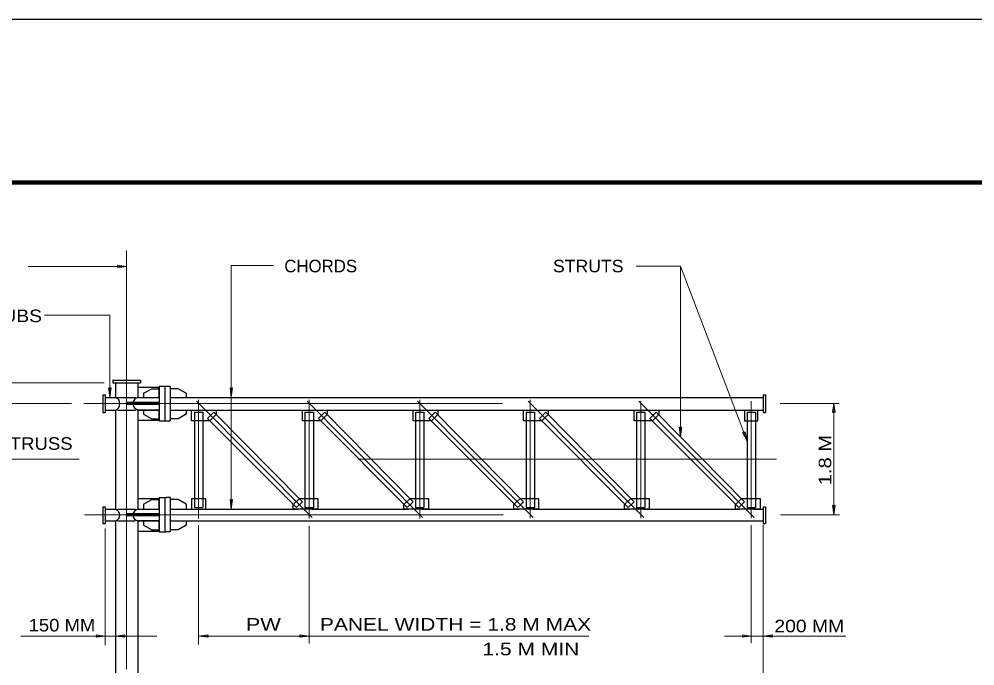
# Model space of a CAD drawing. Extents: x 312601.858 to 312602.699, y 144420.109 to 144420.704.
# Drawn here: x 312601.9725 to 312602.2008, y 144420.549 to 144420.7035 of the extents above; entities that cross this region are included whole.
import ezdxf
from ezdxf.enums import TextEntityAlignment as Align

# ---------------------------------------------------------------- set-up
doc = ezdxf.new("R2010")
doc.units = 0
doc.header["$LTSCALE"] = 0.0012
doc.linetypes.add('DOT_DASHED', pattern=[7.7, 5, -1.2, 0.3, -1.2])
doc.linetypes.add('MEDIUM_DASHED', pattern=[4.5, 3, -1.5])
for name, color, linetype, lineweight in [('1', 7, 'Continuous', 13), ('2', 7, 'Continuous', 25), ('39', 7, 'Continuous', 13)]:
    doc.layers.add(name, color=color, linetype=linetype, lineweight=lineweight)

msp = doc.modelspace()

# ---------------------------------------------------------------- linework, layer by layer
at = {"layer": '1', "linetype": 'DOT_DASHED'}
for p, q in [((312601.9982, 144420.6482), (312601.9982, 144420.4826)), ((312602.0425, 144420.5844), (312602.0149, 144420.6122)), ((312602.0154, 144420.6125), (312602.0154, 144420.5842)), ((312602.0689, 144420.5844), (312602.0413, 144420.6122)), ((312602.0418, 144420.6125), (312602.0418, 144420.5842)), ((312602.0953, 144420.5844), (312602.0677, 144420.6122)), ((312602.0682, 144420.6125), (312602.0682, 144420.5842)), ((312602.1217, 144420.5844), (312602.0941, 144420.6122)), ((312602.0946, 144420.6125), (312602.0946, 144420.5843)), ((312602.1481, 144420.5844), (312602.1205, 144420.6122)), ((312602.121, 144420.6122), (312602.121, 144420.5843)), ((312602.1474, 144420.6122), (312602.1474, 144420.5843)), ((312601.988, 144420.6117), (312602.1531, 144420.6117)), ((312602.1534, 144420.5984), (312601.9892, 144420.5984)), ((312601.9881, 144420.5851), (312602.153, 144420.5851)), ((312602.0154, 144420.5811), (312602.0154, 144420.581))]:
    msp.add_line(p, q, dxfattribs=at)
at = {"layer": '1'}
for p, q in [((312601.9747, 144420.6444), (312601.9982, 144420.6444)), ((312602.0333, 144420.6446), (312602.0232, 144420.6446)), ((312602.1305, 144420.6445), (312602.1464, 144420.6027)), ((312601.9942, 144420.6328), (312601.9786, 144420.6328)), ((312601.9942, 144420.6328), (312601.9942, 144420.6131)), ((312601.9675, 144420.6166), (312601.9928, 144420.6166)), ((312601.9955, 144420.6166), (312602.0009, 144420.6166)), ((312602.0022, 144420.6141), (312602.0042, 144420.6152)), ((312602.0042, 144420.6152), (312602.0053, 144420.6152)), ((312602.0105, 144420.6152), (312602.0093, 144420.6152)), ((312601.9931, 144420.6131), (312601.9931, 144420.6103)), ((312602.0022, 144420.6141), (312602.0022, 144420.6131)), ((312602.0124, 144420.6141), (312602.0124, 144420.6132)), ((312602.0124, 144420.6141), (312602.0124, 144420.6131)), ((312601.9402, 144420.6117), (312601.985, 144420.6117)), ((312602.0464, 144420.6101), (312602.047, 144420.6101)), ((312602.0728, 144420.6101), (312602.0734, 144420.6101)), ((312602.099, 144420.6101), (312602.0998, 144420.6101)), ((312602.1543, 144420.6117), (312602.1684, 144420.6117)), ((312602.1671, 144420.6117), (312602.1671, 144420.5851)), ((312602.0022, 144420.6091), (312602.0042, 144420.608)), ((312602.0042, 144420.608), (312602.0053, 144420.608)), ((312602.0105, 144420.608), (312602.0093, 144420.608)), ((312602.0124, 144420.6091), (312602.0105, 144420.608)), ((312602.0408, 144420.6094), (312602.0408, 144420.6093)), ((312602.0672, 144420.6094), (312602.0672, 144420.6093)), ((312602.0936, 144420.6094), (312602.0936, 144420.6093)), ((312602.12, 144420.6094), (312602.12, 144420.6093)), ((312601.9869, 144420.5984), (312601.9398, 144420.5984)), ((312602.0022, 144420.5876), (312602.0042, 144420.5887)), ((312602.0022, 144420.5876), (312602.0042, 144420.5887)), ((312602.0022, 144420.5876), (312602.0022, 144420.5866)), ((312602.0022, 144420.5876), (312602.0022, 144420.5866)), ((312602.0042, 144420.5887), (312602.0053, 144420.5887)), ((312602.0042, 144420.5887), (312602.0053, 144420.5887)), ((312602.0105, 144420.5887), (312602.0093, 144420.5887)), ((312602.0105, 144420.5887), (312602.0093, 144420.5887)), ((312602.0124, 144420.5876), (312602.0105, 144420.5887)), ((312602.0124, 144420.5876), (312602.0105, 144420.5887)), ((312602.0124, 144420.5876), (312602.0124, 144420.5866)), ((312602.0124, 144420.5876), (312602.0124, 144420.5867)), ((312602.0124, 144420.5876), (312602.0124, 144420.5866)), ((312602.0124, 144420.5876), (312602.0124, 144420.5867)), ((312602.0124, 144420.5876), (312602.0124, 144420.5866)), ((312602.0392, 144420.5864), (312602.0386, 144420.5864)), ((312602.0425, 144420.5864), (312602.047, 144420.5864)), ((312602.0656, 144420.5864), (312602.065, 144420.5864)), ((312602.0655, 144420.5864), (312602.0656, 144420.5864)), ((312602.092, 144420.5864), (312602.0914, 144420.5864)), ((312602.0953, 144420.5864), (312602.0998, 144420.5864)), ((312602.1184, 144420.5864), (312602.1178, 144420.5864)), ((312602.1183, 144420.5864), (312602.1184, 144420.5864)), ((312602.1447, 144420.5864), (312602.1448, 144420.5864)), ((312602.1544, 144420.5851), (312602.1685, 144420.5851)), ((312602.0022, 144420.5836), (312602.0022, 144420.5826)), ((312602.0022, 144420.5826), (312602.0042, 144420.5815)), ((312602.0022, 144420.5826), (312602.0042, 144420.5815)), ((312602.0124, 144420.5826), (312602.0105, 144420.5815)), ((312602.0124, 144420.5826), (312602.0105, 144420.5815)), ((312602.0124, 144420.5836), (312602.0124, 144420.5826)), ((312602.0124, 144420.5836), (312602.0124, 144420.5826)), ((312602.0154, 144420.5826), (312602.0154, 144420.5541)), ((312602.0418, 144420.5824), (312602.0418, 144420.5543)), ((312602.1474, 144420.5826), (312602.1474, 144420.5544)), ((312602.1502, 144420.5827), (312602.1502, 144420.531)), ((312601.9931, 144420.5818), (312601.9931, 144420.5539)), ((312602.0042, 144420.5815), (312602.0053, 144420.5815)), ((312602.0105, 144420.5815), (312602.0093, 144420.5815)), ((312602.0105, 144420.5815), (312602.0093, 144420.5815))]:
    msp.add_line(p, q, dxfattribs=at)
at = {"layer": '1', "lineweight": 25}
for p, q in [((312601.9949, 144420.6172), (312601.9949, 144420.6166)), ((312601.9949, 144420.6166), (312602.0015, 144420.6166)), ((312601.9955, 144420.6166), (312601.9955, 144420.6131)), ((312602.0009, 144420.6166), (312602.0009, 144420.6131)), ((312602.0022, 144420.6141), (312602.0042, 144420.6152)), ((312602.0042, 144420.6152), (312602.006, 144420.6152)), ((312602.0086, 144420.6157), (312602.006, 144420.6157)), ((312602.0105, 144420.6152), (312602.0086, 144420.6152)), ((312602.0124, 144420.6141), (312602.0105, 144420.6152)), ((312602.0124, 144420.6141), (312602.0105, 144420.6152)), ((312601.9925, 144420.6137), (312601.9931, 144420.6137)), ((312601.9925, 144420.6137), (312601.9925, 144420.6095)), ((312601.9931, 144420.6137), (312601.9931, 144420.6095)), ((312601.9931, 144420.6131), (312601.9955, 144420.6131)), ((312602.0009, 144420.6131), (312602.006, 144420.6131)), ((312602.0022, 144420.6141), (312602.0022, 144420.6131)), ((312602.0086, 144420.6131), (312602.1502, 144420.6131)), ((312602.0124, 144420.6141), (312602.0124, 144420.6132)), ((312602.0124, 144420.6141), (312602.0124, 144420.6131)), ((312602.1502, 144420.6137), (312602.1502, 144420.6095)), ((312602.1502, 144420.6137), (312602.1508, 144420.6137)), ((312602.1508, 144420.6137), (312602.1508, 144420.6095)), ((312601.9931, 144420.6101), (312601.9955, 144420.6101)), ((312601.9955, 144420.6101), (312601.9955, 144420.5864)), ((312602.0009, 144420.6101), (312602.0009, 144420.5864)), ((312602.0009, 144420.6101), (312602.006, 144420.6101)), ((312602.0022, 144420.6101), (312602.0022, 144420.6091)), ((312602.0086, 144420.6101), (312602.0124, 144420.6101)), ((312602.0124, 144420.6101), (312602.0148, 144420.6101)), ((312602.0124, 144420.6101), (312602.0124, 144420.6091)), ((312602.0124, 144420.6101), (312602.0124, 144420.6091)), ((312602.0144, 144420.6096), (312602.0144, 144420.5868)), ((312602.0164, 144420.6096), (312602.0164, 144420.5868)), ((312602.0402, 144420.5882), (312602.019, 144420.6096)), ((312602.0408, 144420.6096), (312602.0408, 144420.5868)), ((312602.0428, 144420.6096), (312602.0428, 144420.5868)), ((312602.0449, 144420.6101), (312602.0676, 144420.6101)), ((312602.0666, 144420.5882), (312602.0455, 144420.6096)), ((312602.0672, 144420.6096), (312602.0672, 144420.5868)), ((312602.0692, 144420.6096), (312602.0692, 144420.5868)), ((312602.0714, 144420.6101), (312602.094, 144420.6101)), ((312602.093, 144420.5882), (312602.0719, 144420.6096)), ((312602.0936, 144420.6096), (312602.0936, 144420.5868)), ((312602.0956, 144420.6096), (312602.0956, 144420.5868)), ((312602.0977, 144420.6101), (312602.1204, 144420.6101)), ((312602.1194, 144420.5882), (312602.0983, 144420.6096)), ((312602.12, 144420.6096), (312602.12, 144420.5868)), ((312602.122, 144420.6096), (312602.122, 144420.5868)), ((312602.1241, 144420.6101), (312602.1502, 144420.6101)), ((312602.1458, 144420.5882), (312602.1247, 144420.6096)), ((312602.1253, 144420.6101), (312602.1262, 144420.6101)), ((312602.1464, 144420.6096), (312602.1464, 144420.5868)), ((312602.1484, 144420.6096), (312602.1484, 144420.5868)), ((312601.9925, 144420.6095), (312601.9931, 144420.6095)), ((312602.0022, 144420.6091), (312602.0042, 144420.608)), ((312602.0042, 144420.608), (312602.006, 144420.608)), ((312602.006, 144420.6075), (312602.0086, 144420.6075)), ((312602.0105, 144420.608), (312602.0086, 144420.608)), ((312602.0124, 144420.6091), (312602.0105, 144420.608)), ((312602.0144, 144420.6094), (312602.0144, 144420.6093)), ((312602.0388, 144420.5868), (312602.0175, 144420.6081)), ((312602.0652, 144420.5868), (312602.044, 144420.6081)), ((312602.0916, 144420.5868), (312602.0704, 144420.6081)), ((312602.118, 144420.5868), (312602.0968, 144420.6081)), ((312602.1444, 144420.5868), (312602.1232, 144420.6081)), ((312602.1502, 144420.6095), (312602.1508, 144420.6095)), ((312602.006, 144420.5892), (312602.0077, 144420.5892)), ((312602.0086, 144420.5892), (312602.0077, 144420.5892)), ((312601.9925, 144420.587), (312601.9925, 144420.583)), ((312601.9925, 144420.587), (312601.9931, 144420.587)), ((312601.9931, 144420.587), (312601.9931, 144420.583)), ((312602.0022, 144420.5876), (312602.0042, 144420.5887)), ((312602.0022, 144420.5876), (312602.0022, 144420.5864)), ((312602.0042, 144420.5887), (312602.006, 144420.5887)), ((312602.0105, 144420.5887), (312602.0086, 144420.5887)), ((312602.0124, 144420.5876), (312602.0105, 144420.5887)), ((312602.0124, 144420.5876), (312602.0124, 144420.5864)), ((312602.1502, 144420.587), (312602.1502, 144420.583)), ((312602.1502, 144420.587), (312602.1508, 144420.587)), ((312602.1508, 144420.587), (312602.1508, 144420.583)), ((312601.9931, 144420.5864), (312601.9955, 144420.5864)), ((312602.0009, 144420.5864), (312602.006, 144420.5864)), ((312602.0086, 144420.5864), (312602.0161, 144420.5864)), ((312602.016, 144420.5864), (312602.0392, 144420.5864)), ((312602.0424, 144420.5864), (312602.0656, 144420.5864)), ((312602.0688, 144420.5864), (312602.092, 144420.5864)), ((312602.0689, 144420.5864), (312602.0734, 144420.5864)), ((312602.0952, 144420.5864), (312602.1184, 144420.5864)), ((312602.1216, 144420.5864), (312602.1447, 144420.5864)), ((312602.1217, 144420.5864), (312602.1262, 144420.5864)), ((312602.148, 144420.5864), (312602.1502, 144420.5864)), ((312601.9925, 144420.583), (312601.9931, 144420.583)), ((312601.9931, 144420.5836), (312601.9955, 144420.5836)), ((312601.9955, 144420.5836), (312601.9955, 144420.4967)), ((312602.0009, 144420.5836), (312602.0009, 144420.4967)), ((312602.0009, 144420.5836), (312602.006, 144420.5836)), ((312602.0022, 144420.5836), (312602.0022, 144420.5826)), ((312602.0022, 144420.5826), (312602.0042, 144420.5815)), ((312602.0086, 144420.5836), (312602.0124, 144420.5836)), ((312602.0124, 144420.5826), (312602.0105, 144420.5815)), ((312602.0122, 144420.5836), (312602.1502, 144420.5836)), ((312602.0124, 144420.5836), (312602.0124, 144420.5826)), ((312602.1502, 144420.583), (312602.1508, 144420.583)), ((312602.0042, 144420.5815), (312602.006, 144420.5815)), ((312602.006, 144420.581), (312602.0077, 144420.581)), ((312602.0086, 144420.581), (312602.0077, 144420.581)), ((312602.0105, 144420.5815), (312602.0086, 144420.5815))]:
    msp.add_line(p, q, dxfattribs=at)
at = {"layer": '1', "linetype": 'MEDIUM_DASHED', "lineweight": 25}
for p, q in [((312601.9959, 144420.6131), (312602.0004, 144420.6131)), ((312601.996, 144420.6101), (312602.0003, 144420.6101)), ((312601.996, 144420.5864), (312602.0003, 144420.5864)), ((312601.996, 144420.5836), (312602.0002, 144420.5836))]:
    msp.add_line(p, q, dxfattribs=at)
at = {"layer": '1'}
for points in [[(312601.996, 144420.6447), (312601.9982, 144420.6444), (312601.996, 144420.6441), (312601.9962, 144420.6444)], [(312601.996, 144420.6447), (312601.9982, 144420.6444), (312601.996, 144420.6441), (312601.9962, 144420.6444)], [(312601.9945, 144420.6154), (312601.9942, 144420.6131), (312601.9939, 144420.6154), (312601.9942, 144420.6151)], [(312601.9945, 144420.6154), (312601.9942, 144420.6131), (312601.9939, 144420.6154), (312601.9942, 144420.6151)], [(312602.0235, 144420.6154), (312602.0232, 144420.6131), (312602.0229, 144420.6154), (312602.0232, 144420.6151)], [(312602.1668, 144420.6095), (312602.1671, 144420.6117), (312602.1674, 144420.6095), (312602.1671, 144420.6097)], [(312602.1668, 144420.6095), (312602.1671, 144420.6117), (312602.1674, 144420.6095), (312602.1671, 144420.6097)], [(312602.1308, 144420.606), (312602.1305, 144420.6037), (312602.1302, 144420.606), (312602.1305, 144420.6057)], [(312602.1308, 144420.606), (312602.1305, 144420.6037), (312602.1302, 144420.606), (312602.1305, 144420.6057)], [(312602.1459, 144420.6049), (312602.1464, 144420.6027), (312602.1453, 144420.6047), (312602.1457, 144420.6046)], [(312602.1459, 144420.6049), (312602.1464, 144420.6027), (312602.1453, 144420.6047), (312602.1457, 144420.6046)], [(312602.0235, 144420.5887), (312602.0232, 144420.5864), (312602.0229, 144420.5887), (312602.0232, 144420.5884)], [(312602.0235, 144420.5887), (312602.0232, 144420.5864), (312602.0229, 144420.5887), (312602.0232, 144420.5884)], [(312602.1674, 144420.5874), (312602.1671, 144420.5851), (312602.1668, 144420.5874), (312602.1671, 144420.5871)], [(312602.1674, 144420.5874), (312602.1671, 144420.5851), (312602.1668, 144420.5874), (312602.1671, 144420.5871)], [(312601.9909, 144420.5564), (312601.9931, 144420.5561), (312601.9909, 144420.5558), (312601.9911, 144420.5561)], [(312601.9978, 144420.5558), (312601.9955, 144420.5561), (312601.9978, 144420.5564), (312601.9975, 144420.5561)], [(312602.0177, 144420.5558), (312602.0154, 144420.5561), (312602.0177, 144420.5564), (312602.0174, 144420.5561)], [(312602.0396, 144420.5564), (312602.0418, 144420.5561), (312602.0396, 144420.5558), (312602.0398, 144420.5561)], [(312602.1452, 144420.5564), (312602.1474, 144420.5561), (312602.1452, 144420.5558), (312602.1454, 144420.5561)], [(312602.1525, 144420.5558), (312602.1502, 144420.5561), (312602.1525, 144420.5564), (312602.1522, 144420.5561)], [(312602.1525, 144420.5558), (312602.1502, 144420.5561), (312602.1525, 144420.5564), (312602.1522, 144420.5561)]]:
    msp.add_lwpolyline(points, close=True, dxfattribs=at)
for points in [[(312602.0232, 144420.6446), (312602.0232, 144420.6131), (312602.0232, 144420.5864)], [(312602.1199, 144420.6445), (312602.1305, 144420.6445), (312602.1305, 144420.6037)], [(312602.0919, 144420.5864), (312602.092, 144420.5864), (312602.092, 144420.5864)], [(312602.1183, 144420.5864), (312602.1184, 144420.5864), (312602.1184, 144420.5864)], [(312601.9729, 144420.5561), (312601.9931, 144420.5561), (312601.9955, 144420.5561), (312602.0054, 144420.5561)], [(312602.0154, 144420.5561), (312602.0418, 144420.5561), (312602.1086, 144420.5561)], [(312602.141, 144420.5561), (312602.1474, 144420.5561), (312602.1501, 144420.5561), (312602.17, 144420.5561)]]:
    msp.add_lwpolyline(points, dxfattribs=at)
at = {"layer": '1', "lineweight": 25}
msp.add_lwpolyline([(312601.9949, 144420.6172), (312602.0015, 144420.6172), (312602.0015, 144420.6166)], dxfattribs=at)
for points in [[(312602.0009, 144420.6131), (312602.006, 144420.6131), (312602.006, 144420.6155), (312602.0009, 144420.6155)], [(312601.9982, 144420.6115), (312602.006, 144420.6115), (312602.006, 144420.6119), (312601.9982, 144420.6119)], [(312602.0009, 144420.6077), (312602.006, 144420.6077), (312602.006, 144420.6101), (312602.0009, 144420.6101)], [(312602.0009, 144420.5864), (312602.006, 144420.5864), (312602.006, 144420.5889), (312602.0009, 144420.5889)], [(312601.9982, 144420.5849), (312602.006, 144420.5849), (312602.006, 144420.5853), (312601.9982, 144420.5853)], [(312602.0009, 144420.5812), (312602.006, 144420.5812), (312602.006, 144420.5836), (312602.0009, 144420.5836)]]:
    msp.add_lwpolyline(points, close=True, dxfattribs=at)
for centre, radius, start, end in [((312601.995032, 144420.6116), 0.0015714, 287.33425, 72.66575), ((312602.001233, 144420.6116), 0.0015366, 102.52881, 168.93478), ((312602.001233, 144420.6116), 0.0015366, 183.81131, 257.47119), ((312601.995164, 144420.585), 0.0014398, 283.5098, 76.49019), ((312602.001113, 144420.585), 0.001416, 179.71208, 180.30501), ((312602.001113, 144420.585), 0.001416, 184.13614, 261.3692), ((312602.001113, 144420.585), 0.001416, 98.6308, 170.66727)]:
    msp.add_arc(centre, radius, start, end, dxfattribs=at)
at = {"layer": '2'}
for p, q in [((312602.006, 144420.6157), (312602.006, 144420.6075)), ((312602.0073, 144420.6157), (312602.0073, 144420.6075)), ((312602.0086, 144420.6157), (312602.0086, 144420.6075)), ((312602.0086, 144420.6101), (312602.1137, 144420.6101)), ((312602.0144, 144420.6096), (312602.0164, 144420.6096)), ((312602.0175, 144420.6081), (312602.019, 144420.6096)), ((312602.0408, 144420.6096), (312602.0428, 144420.6096)), ((312602.0455, 144420.6096), (312602.044, 144420.6081)), ((312602.0672, 144420.6096), (312602.0692, 144420.6096)), ((312602.0719, 144420.6096), (312602.0704, 144420.6081)), ((312602.0936, 144420.6096), (312602.0956, 144420.6096)), ((312602.0983, 144420.6096), (312602.0968, 144420.6081)), ((312602.12, 144420.6096), (312602.122, 144420.6096)), ((312602.1247, 144420.6096), (312602.1232, 144420.6081)), ((312602.1464, 144420.6096), (312602.1484, 144420.6096)), ((312602.006, 144420.5892), (312602.006, 144420.581)), ((312602.0073, 144420.5892), (312602.0073, 144420.581)), ((312602.0086, 144420.5892), (312602.0086, 144420.581)), ((312602.0144, 144420.5868), (312602.0164, 144420.5868)), ((312602.0388, 144420.5868), (312602.0402, 144420.5882)), ((312602.0408, 144420.5868), (312602.0428, 144420.5868)), ((312602.0652, 144420.5868), (312602.0666, 144420.5882)), ((312602.0672, 144420.5868), (312602.0692, 144420.5868)), ((312602.0916, 144420.5868), (312602.093, 144420.5882)), ((312602.0936, 144420.5868), (312602.0956, 144420.5868)), ((312602.118, 144420.5868), (312602.1194, 144420.5882)), ((312602.12, 144420.5868), (312602.122, 144420.5868)), ((312602.1444, 144420.5868), (312602.1458, 144420.5882)), ((312602.1464, 144420.5868), (312602.1484, 144420.5868))]:
    msp.add_line(p, q, dxfattribs=at)
for points in [[(312602.0137, 144420.6101), (312602.0196, 144420.6101), (312602.0196, 144420.609), (312602.0181, 144420.6075), (312602.0137, 144420.6075)], [(312602.0402, 144420.6101), (312602.0461, 144420.6101), (312602.0461, 144420.609), (312602.0446, 144420.6075), (312602.0402, 144420.6075)], [(312602.0666, 144420.6101), (312602.0725, 144420.6101), (312602.0725, 144420.609), (312602.071, 144420.6075), (312602.0666, 144420.6075)], [(312602.093, 144420.6101), (312602.0989, 144420.6101), (312602.0989, 144420.609), (312602.0974, 144420.6075), (312602.093, 144420.6075)], [(312602.1194, 144420.6101), (312602.1253, 144420.6101), (312602.1253, 144420.609), (312602.1238, 144420.6075), (312602.1194, 144420.6075)], [(312602.0439, 144420.5864), (312602.038, 144420.5864), (312602.038, 144420.5875), (312602.0395, 144420.589), (312602.0439, 144420.589)], [(312602.0703, 144420.5864), (312602.0644, 144420.5864), (312602.0644, 144420.5875), (312602.0659, 144420.589), (312602.0703, 144420.589)], [(312602.0966, 144420.5864), (312602.0907, 144420.5864), (312602.0907, 144420.5875), (312602.0922, 144420.589), (312602.0966, 144420.589)], [(312602.123, 144420.5864), (312602.1171, 144420.5864), (312602.1171, 144420.5875), (312602.1186, 144420.589), (312602.123, 144420.589)], [(312602.1495, 144420.5864), (312602.1436, 144420.5864), (312602.1436, 144420.5875), (312602.1451, 144420.589), (312602.1495, 144420.589)]]:
    msp.add_lwpolyline(points, close=True, dxfattribs=at)
for points in [[(312602.1458, 144420.6101), (312602.1458, 144420.6075), (312602.149, 144420.6075), (312602.149, 144420.6101)], [(312602.0138, 144420.5864), (312602.0138, 144420.589), (312602.017, 144420.589), (312602.017, 144420.5864)]]:
    msp.add_lwpolyline(points, dxfattribs=at)
at = {"layer": '39', "lineweight": 25}
msp.add_line((312601.8578, 144420.7035), (312602.6988, 144420.7035), dxfattribs=at)
at = {"layer": '39', "lineweight": 158}
msp.add_line((312601.9088, 144420.6645), (312602.6838, 144420.6645), dxfattribs=at)

# ---------------------------------------------------------------- texts
at = {"layer": '2'}
msp.add_text('CHORDS', height=0.003, dxfattribs=at).set_placement((312602.04455, 144420.643), align=Align.CENTER)
for s, width, p in [('STRUTS', 1.05, (312602.10845, 144420.643)), ('STEEL STUBS', 1.15, (312601.96235, 144420.6311)), ('C TRUSS', 1.1, (312601.9756, 144420.6006)), ('150 MM', 1.1, (312601.98275, 144420.5572)), ('PW  ', 1.3, (312602.0323, 144420.5574)), ('PANEL WIDTH = 1.8 M MAX ', 1.25, (312602.07745, 144420.5574)), ('200 MM', 1.15, (312602.16125, 144420.557)), ('1.5 M MIN', 1.25, (312602.09475, 144420.5515))]:
    msp.add_text(s, height=0.003, dxfattribs=dict(at, width=width)).set_placement(p, align=Align.CENTER)
at = {"layer": '2', "width": 1.2}
msp.add_text('1.8 M', height=0.003, rotation=90, dxfattribs=at).set_placement((312602.1665, 144420.59815), align=Align.CENTER)

doc.saveas('drawing.dxf')
